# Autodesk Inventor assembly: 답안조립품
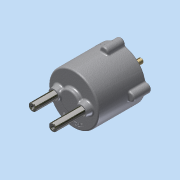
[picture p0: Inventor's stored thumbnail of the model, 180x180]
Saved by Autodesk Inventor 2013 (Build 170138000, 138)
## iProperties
Created: 2015-02
Part Number: 답안조립품
Document SubType Name: Assembly
Designer: WINDOWS7
Author: WINDOWS7
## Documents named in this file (13)
- C:\Users\WINDOWS7\Desktop\350208V1007\답안조립품.iam
- C:\Users\WINDOWS7\Desktop\350208V1007\몸체.ipt
- C:\Users\WINDOWS7\Desktop\350208V1007\베어링 NA 4900.ipt
- C:\Users\WINDOWS7\Desktop\350208V1007\커버.ipt
- C:\Users\WINDOWS7\Desktop\350208V1007\오일실.ipt
- C:\Users\WINDOWS7\Desktop\350208V1007\M5x0.5x20.ipt
- C:\Users\WINDOWS7\Desktop\350208V1007\메인 축.ipt
- C:\Users\WINDOWS7\Desktop\350208V1007\멈춤링 10 x 1.ipt
- C:\Users\WINDOWS7\Desktop\350208V1007\멈춤링 22 x 1.2.ipt
- C:\Users\WINDOWS7\Desktop\350208V1007\판캠.ipt
- C:\Users\WINDOWS7\Desktop\350208V1007\슬라이드 축.ipt
- C:\Users\WINDOWS7\Desktop\350208V1007\11 가변 스프링.ipt
- C:\Users\WINDOWS7\Desktop\350208V1007\12 가변 스프링.ipt
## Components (6 placed, 3 different names)
1. 11 가변 스프링:1
2. 12 가변 스프링:1
3. M5x0.5x20:1
4. M5x0.5x20:2
5. M5x0.5x20:3
6. M5x0.5x20:4
